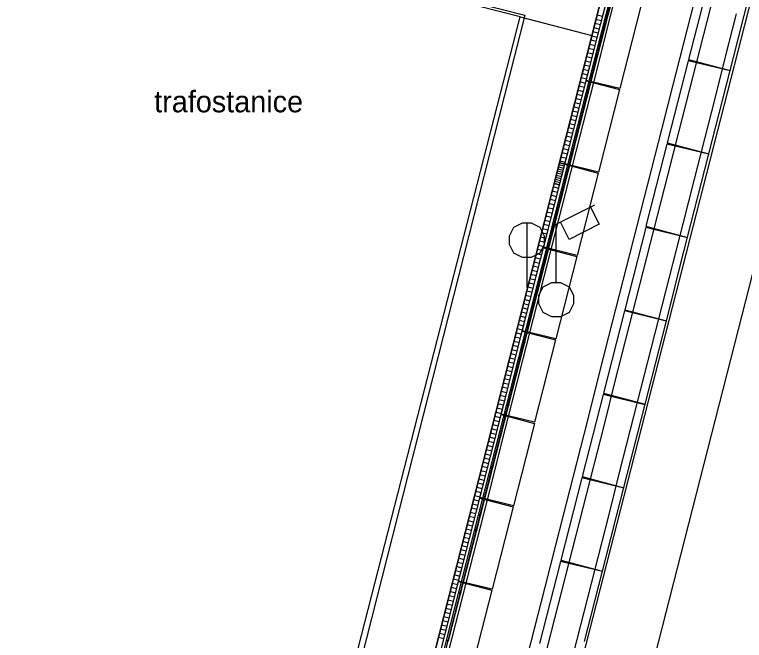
# Model space of a CAD drawing. Extents: x -733601 to -733291, y -1137892 to -1137187.
# Drawn here: x -733477.5 to -733460.56, y -1137708.26 to -1137693.72 of the extents above; entities that cross this region are included whole.
import ezdxf

# ---------------------------------------------------------------- set-up
doc = ezdxf.new("R2010")
doc.units = 0
doc.layers.add('SIT_PUV_BUS', color=7, linetype='Continuous')
doc.layers.add('SIT_PUV_ZELEZNICE', color=7, linetype='Continuous')

msp = doc.modelspace()

# ---------------------------------------------------------------- linework, layer by layer
at = {"layer": 'SIT_PUV_BUS'}
for p, q in [((-733452.43, -1137662.15), (-733466.53, -1137717.32)), ((-733460.18, -1137679.73), (-733469.47, -1137716.2)), ((-733477.5, -1137690.71), (-733465.66, -1137693.73)), ((-733465.66, -1137693.73), (-733470.86, -1137714.23)), ((-733464.93, -1137698.59), (-733464.03, -1137698.14)), ((-733464.13, -1137698.19), (-733463.93, -1137698.59)), ((-733465.91, -1137698.66), (-733465.71, -1137698.56)), ((-733465.71, -1137698.56), (-733465.51, -1137698.56)), ((-733465.61, -1137698.56), (-733465.61, -1137700.06)), ((-733465.51, -1137698.56), (-733465.31, -1137698.66)), ((-733464.93, -1137699.94), (-733464.93, -1137698.59)), ((-733464.63, -1137698.94), (-733464.83, -1137698.54)), ((-733463.93, -1137698.59), (-733464.63, -1137698.94)), ((-733466.01, -1137698.86), (-733465.91, -1137698.66)), ((-733465.31, -1137698.66), (-733465.21, -1137698.86)), ((-733466.01, -1137699.06), (-733466.01, -1137698.86)), ((-733465.21, -1137698.86), (-733465.21, -1137699.06)), ((-733465.91, -1137699.26), (-733466.01, -1137699.06)), ((-733465.21, -1137699.06), (-733465.31, -1137699.26)), ((-733465.71, -1137699.36), (-733465.91, -1137699.26)), ((-733465.31, -1137699.26), (-733465.51, -1137699.36)), ((-733465.51, -1137699.36), (-733465.71, -1137699.36)), ((-733465.23, -1137700.04), (-733465.03, -1137699.94)), ((-733465.03, -1137699.94), (-733464.83, -1137699.94)), ((-733464.83, -1137699.94), (-733464.63, -1137700.04)), ((-733465.33, -1137700.24), (-733465.23, -1137700.04)), ((-733464.63, -1137700.04), (-733464.53, -1137700.24)), ((-733465.33, -1137700.44), (-733465.33, -1137700.24)), ((-733464.53, -1137700.24), (-733464.53, -1137700.44)), ((-733465.23, -1137700.64), (-733465.33, -1137700.44)), ((-733464.53, -1137700.44), (-733464.63, -1137700.64)), ((-733465.03, -1137700.74), (-733465.23, -1137700.64)), ((-733464.63, -1137700.64), (-733464.83, -1137700.74)), ((-733464.83, -1137700.74), (-733465.03, -1137700.74))]:
    msp.add_line(p, q, dxfattribs=at)
at = {"layer": 'SIT_PUV_ZELEZNICE'}
for p, q in [((-733463.769, -1137693.72), (-733463.028, -1137690.812)), ((-733463.722, -1137693.732), (-733462.982, -1137690.824)), ((-733461.371, -1137692.852), (-733461.858, -1137694.761)), ((-733462.967, -1137693.525), (-733463.454, -1137695.437)), ((-733464.509, -1137696.627), (-733463.769, -1137693.72)), ((-733463.769, -1137693.72), (-733463.722, -1137693.732)), ((-733463.722, -1137693.732), (-733463.769, -1137693.72)), ((-733465.765, -1137693.775), (-733464.1, -1137694.204)), ((-733464.463, -1137696.639), (-733463.722, -1137693.732)), ((-733463.879, -1137693.863), (-733464.005, -1137693.831)), ((-733463.854, -1137693.766), (-733463.98, -1137693.734)), ((-733463.928, -1137694.057), (-733464.054, -1137694.025)), ((-733463.903, -1137693.96), (-733464.029, -1137693.928)), ((-733463.977, -1137694.251), (-733464.103, -1137694.219)), ((-733463.953, -1137694.154), (-733464.079, -1137694.122)), ((-733464.002, -1137694.348), (-733464.128, -1137694.316)), ((-733464.051, -1137694.541), (-733464.177, -1137694.509)), ((-733464.027, -1137694.445), (-733464.153, -1137694.412)), ((-733464.101, -1137694.735), (-733464.227, -1137694.703)), ((-733464.076, -1137694.638), (-733464.202, -1137694.606)), ((-733464.15, -1137694.929), (-733464.276, -1137694.897)), ((-733464.125, -1137694.832), (-733464.251, -1137694.8)), ((-733461.865, -1137694.79), (-733462.351, -1137696.699)), ((-733460.894, -1137695.027), (-733461.865, -1137694.79)), ((-733461.858, -1137694.761), (-733460.891, -1137695.018)), ((-733464.175, -1137695.026), (-733464.301, -1137694.994)), ((-733464.224, -1137695.22), (-733464.35, -1137695.188)), ((-733464.199, -1137695.123), (-733464.325, -1137695.091)), ((-733463.454, -1137695.437), (-733464.231, -1137695.248)), ((-733464.274, -1137695.414), (-733464.4, -1137695.382)), ((-733464.249, -1137695.317), (-733464.375, -1137695.285)), ((-733464.234, -1137695.257), (-733463.46, -1137695.463)), ((-733464.323, -1137695.607), (-733464.449, -1137695.575)), ((-733464.298, -1137695.511), (-733464.424, -1137695.478)), ((-733463.46, -1137695.463), (-733463.948, -1137697.376)), ((-733464.348, -1137695.704), (-733464.474, -1137695.672)), ((-733464.397, -1137695.898), (-733464.523, -1137695.866)), ((-733464.372, -1137695.801), (-733464.498, -1137695.769)), ((-733464.446, -1137696.092), (-733464.572, -1137696.06)), ((-733464.422, -1137695.995), (-733464.548, -1137695.963)), ((-733464.496, -1137696.286), (-733464.622, -1137696.254)), ((-733464.471, -1137696.189), (-733464.597, -1137696.157)), ((-733464.52, -1137696.383), (-733464.646, -1137696.351)), ((-733464.57, -1137696.576), (-733464.696, -1137696.544)), ((-733464.545, -1137696.48), (-733464.671, -1137696.447)), ((-733465.25, -1137699.534), (-733464.509, -1137696.627)), ((-733465.203, -1137699.546), (-733464.463, -1137696.639)), ((-733464.619, -1137696.77), (-733464.745, -1137696.738)), ((-733464.594, -1137696.673), (-733464.72, -1137696.641)), ((-733464.509, -1137696.627), (-733464.463, -1137696.639)), ((-733464.463, -1137696.639), (-733464.509, -1137696.627)), ((-733462.359, -1137696.728), (-733462.845, -1137698.637)), ((-733461.387, -1137696.965), (-733462.359, -1137696.728)), ((-733462.351, -1137696.699), (-733461.385, -1137696.956)), ((-733464.668, -1137696.964), (-733464.794, -1137696.932)), ((-733464.644, -1137696.867), (-733464.77, -1137696.835)), ((-733464.693, -1137697.061), (-733464.819, -1137697.029)), ((-733464.752, -1137697.292), (-733464.878, -1137697.26)), ((-733464.74, -1137697.244), (-733464.866, -1137697.211)), ((-733464.727, -1137697.195), (-733464.853, -1137697.163)), ((-733464.852, -1137697.159), (-733464.726, -1137697.191)), ((-733464.718, -1137697.158), (-733464.844, -1137697.126)), ((-733464.727, -1137697.196), (-733463.954, -1137697.401)), ((-733463.948, -1137697.376), (-733464.725, -1137697.186)), ((-733464.801, -1137697.486), (-733464.927, -1137697.454)), ((-733464.789, -1137697.437), (-733464.915, -1137697.405)), ((-733464.777, -1137697.389), (-733464.903, -1137697.357)), ((-733464.764, -1137697.34), (-733464.89, -1137697.308)), ((-733463.954, -1137697.401), (-733464.441, -1137699.314)), ((-733464.838, -1137697.631), (-733464.964, -1137697.599)), ((-733464.826, -1137697.583), (-733464.952, -1137697.551)), ((-733464.814, -1137697.534), (-733464.94, -1137697.502)), ((-733464.87, -1137697.756), (-733464.996, -1137697.724)), ((-733464.976, -1137697.643), (-733464.85, -1137697.675)), ((-733464.92, -1137697.95), (-733465.045, -1137697.917)), ((-733464.895, -1137697.853), (-733465.021, -1137697.821)), ((-733464.969, -1137698.143), (-733465.095, -1137698.111)), ((-733464.944, -1137698.046), (-733465.07, -1137698.014)), ((-733464.994, -1137698.24), (-733465.12, -1137698.208)), ((-733465.043, -1137698.434), (-733465.169, -1137698.402)), ((-733465.018, -1137698.337), (-733465.144, -1137698.305)), ((-733465.092, -1137698.628), (-733465.218, -1137698.596)), ((-733465.068, -1137698.531), (-733465.194, -1137698.499)), ((-733462.845, -1137698.637), (-733461.878, -1137698.894)), ((-733465.142, -1137698.822), (-733465.268, -1137698.79)), ((-733465.117, -1137698.725), (-733465.243, -1137698.693)), ((-733462.852, -1137698.666), (-733463.339, -1137700.575)), ((-733461.881, -1137698.903), (-733462.852, -1137698.666)), ((-733465.166, -1137698.919), (-733465.292, -1137698.886)), ((-733465.216, -1137699.112), (-733465.342, -1137699.08)), ((-733465.191, -1137699.015), (-733465.317, -1137698.983)), ((-733465.221, -1137699.134), (-733464.448, -1137699.339)), ((-733464.441, -1137699.314), (-733465.219, -1137699.124)), ((-733465.265, -1137699.306), (-733465.391, -1137699.274)), ((-733465.24, -1137699.209), (-733465.366, -1137699.177)), ((-733465.314, -1137699.5), (-733465.44, -1137699.468)), ((-733465.29, -1137699.403), (-733465.416, -1137699.371)), ((-733464.448, -1137699.339), (-733464.935, -1137701.252)), ((-733465.991, -1137702.441), (-733465.25, -1137699.534)), ((-733465.944, -1137702.453), (-733465.203, -1137699.546)), ((-733465.339, -1137699.597), (-733465.465, -1137699.565)), ((-733465.25, -1137699.534), (-733465.203, -1137699.546)), ((-733465.203, -1137699.546), (-733465.25, -1137699.534)), ((-733465.389, -1137699.791), (-733465.515, -1137699.759)), ((-733465.364, -1137699.694), (-733465.49, -1137699.662)), ((-733465.438, -1137699.985), (-733465.564, -1137699.952)), ((-733465.413, -1137699.888), (-733465.539, -1137699.856)), ((-733465.487, -1137700.178), (-733465.613, -1137700.146)), ((-733465.463, -1137700.081), (-733465.589, -1137700.049)), ((-733465.512, -1137700.275), (-733465.638, -1137700.243)), ((-733465.561, -1137700.469), (-733465.687, -1137700.437)), ((-733465.537, -1137700.372), (-733465.663, -1137700.34)), ((-733465.611, -1137700.663), (-733465.737, -1137700.631)), ((-733465.586, -1137700.566), (-733465.712, -1137700.534)), ((-733463.346, -1137700.604), (-733463.833, -1137702.513)), ((-733462.375, -1137700.842), (-733463.346, -1137700.604)), ((-733463.339, -1137700.575), (-733462.372, -1137700.832)), ((-733465.66, -1137700.857), (-733465.786, -1137700.825)), ((-733465.635, -1137700.76), (-733465.761, -1137700.728)), ((-733465.685, -1137700.954), (-733465.811, -1137700.921)), ((-733465.734, -1137701.147), (-733465.86, -1137701.115)), ((-733465.709, -1137701.05), (-733465.835, -1137701.018)), ((-733465.715, -1137701.072), (-733464.942, -1137701.277)), ((-733464.935, -1137701.252), (-733465.712, -1137701.062)), ((-733465.784, -1137701.341), (-733465.909, -1137701.309)), ((-733465.759, -1137701.244), (-733465.885, -1137701.212)), ((-733464.942, -1137701.277), (-733465.429, -1137703.19)), ((-733465.833, -1137701.535), (-733465.959, -1137701.503)), ((-733465.808, -1137701.438), (-733465.934, -1137701.406)), ((-733465.858, -1137701.632), (-733465.984, -1137701.6)), ((-733465.907, -1137701.826), (-733466.033, -1137701.794)), ((-733465.882, -1137701.729), (-733466.008, -1137701.697)), ((-733465.956, -1137702.02), (-733466.082, -1137701.987)), ((-733465.932, -1137701.923), (-733466.058, -1137701.891)), ((-733466.006, -1137702.213), (-733466.132, -1137702.181)), ((-733465.981, -1137702.116), (-733466.107, -1137702.084)), ((-733466.03, -1137702.31), (-733466.156, -1137702.278)), ((-733466.731, -1137705.348), (-733465.991, -1137702.441)), ((-733466.684, -1137705.36), (-733465.944, -1137702.453)), ((-733466.08, -1137702.504), (-733466.206, -1137702.472)), ((-733466.055, -1137702.407), (-733466.181, -1137702.375)), ((-733465.991, -1137702.441), (-733465.944, -1137702.453)), ((-733465.944, -1137702.453), (-733465.991, -1137702.441)), ((-733463.833, -1137702.513), (-733462.866, -1137702.77)), ((-733466.129, -1137702.698), (-733466.255, -1137702.666)), ((-733466.104, -1137702.601), (-733466.23, -1137702.569)), ((-733463.84, -1137702.542), (-733464.326, -1137704.452)), ((-733462.868, -1137702.78), (-733463.84, -1137702.542)), ((-733466.178, -1137702.892), (-733466.304, -1137702.86)), ((-733466.154, -1137702.795), (-733466.28, -1137702.763)), ((-733466.203, -1137702.989), (-733466.329, -1137702.957)), ((-733466.209, -1137703.01), (-733465.435, -1137703.215)), ((-733465.429, -1137703.19), (-733466.206, -1137703)), ((-733466.253, -1137703.182), (-733466.379, -1137703.15)), ((-733466.228, -1137703.085), (-733466.354, -1137703.053)), ((-733465.435, -1137703.215), (-733465.923, -1137705.128)), ((-733466.302, -1137703.376), (-733466.428, -1137703.344)), ((-733466.277, -1137703.279), (-733466.403, -1137703.247)), ((-733466.351, -1137703.57), (-733466.477, -1137703.538)), ((-733466.327, -1137703.473), (-733466.453, -1137703.441)), ((-733466.376, -1137703.667), (-733466.502, -1137703.635)), ((-733466.425, -1137703.861), (-733466.551, -1137703.829)), ((-733466.401, -1137703.764), (-733466.527, -1137703.732)), ((-733466.475, -1137704.055), (-733466.601, -1137704.022)), ((-733466.45, -1137703.958), (-733466.576, -1137703.926)), ((-733466.524, -1137704.248), (-733466.65, -1137704.216)), ((-733466.499, -1137704.151), (-733466.625, -1137704.119)), ((-733466.549, -1137704.345), (-733466.675, -1137704.313)), ((-733466.598, -1137704.539), (-733466.724, -1137704.507)), ((-733466.573, -1137704.442), (-733466.699, -1137704.41)), ((-733464.334, -1137704.481), (-733464.82, -1137706.39)), ((-733463.362, -1137704.718), (-733464.334, -1137704.481)), ((-733464.326, -1137704.452), (-733463.36, -1137704.708)), ((-733466.648, -1137704.733), (-733466.773, -1137704.701)), ((-733466.623, -1137704.636), (-733466.749, -1137704.604)), ((-733466.697, -1137704.927), (-733466.823, -1137704.895)), ((-733466.672, -1137704.83), (-733466.798, -1137704.798)), ((-733466.722, -1137705.024), (-733466.848, -1137704.992)), ((-733466.702, -1137704.948), (-733465.929, -1137705.153)), ((-733465.923, -1137705.128), (-733466.7, -1137704.938)), ((-733466.771, -1137705.217), (-733466.897, -1137705.185)), ((-733466.746, -1137705.121), (-733466.872, -1137705.088)), ((-733465.929, -1137705.153), (-733466.416, -1137707.066)), ((-733467.472, -1137708.255), (-733466.731, -1137705.348)), ((-733467.425, -1137708.267), (-733466.684, -1137705.36)), ((-733466.82, -1137705.411), (-733466.946, -1137705.379)), ((-733466.796, -1137705.314), (-733466.922, -1137705.282)), ((-733466.731, -1137705.348), (-733466.684, -1137705.36)), ((-733466.684, -1137705.36), (-733466.731, -1137705.348)), ((-733466.87, -1137705.605), (-733466.996, -1137705.573)), ((-733466.845, -1137705.508), (-733466.971, -1137705.476)), ((-733466.894, -1137705.702), (-733467.02, -1137705.67)), ((-733466.944, -1137705.896), (-733467.07, -1137705.864)), ((-733466.919, -1137705.799), (-733467.045, -1137705.767)), ((-733466.993, -1137706.09), (-733467.119, -1137706.057)), ((-733466.968, -1137705.993), (-733467.094, -1137705.961)), ((-733467.042, -1137706.283), (-733467.168, -1137706.251)), ((-733467.018, -1137706.186), (-733467.144, -1137706.154)), ((-733467.067, -1137706.38), (-733467.193, -1137706.348)), ((-733464.827, -1137706.419), (-733465.314, -1137708.328)), ((-733463.856, -1137706.656), (-733464.827, -1137706.419)), ((-733464.82, -1137706.39), (-733463.853, -1137706.646)), ((-733467.117, -1137706.574), (-733467.243, -1137706.542)), ((-733467.092, -1137706.477), (-733467.218, -1137706.445)), ((-733467.166, -1137706.768), (-733467.292, -1137706.736)), ((-733467.141, -1137706.671), (-733467.267, -1137706.639)), ((-733467.215, -1137706.962), (-733467.341, -1137706.93)), ((-733467.191, -1137706.865), (-733467.317, -1137706.833)), ((-733467.196, -1137706.886), (-733466.423, -1137707.091)), ((-733466.416, -1137707.066), (-733467.194, -1137706.876)), ((-733467.24, -1137707.059), (-733467.366, -1137707.027)), ((-733466.423, -1137707.091), (-733466.91, -1137709.004)), ((-733467.289, -1137707.252), (-733467.415, -1137707.22)), ((-733467.265, -1137707.156), (-733467.391, -1137707.123)), ((-733467.339, -1137707.446), (-733467.465, -1137707.414)), ((-733467.314, -1137707.349), (-733467.44, -1137707.317)), ((-733467.388, -1137707.64), (-733467.514, -1137707.608)), ((-733467.363, -1137707.543), (-733467.489, -1137707.511)), ((-733467.413, -1137707.737), (-733467.539, -1137707.705)), ((-733467.462, -1137707.931), (-733467.588, -1137707.899)), ((-733467.437, -1137707.834), (-733467.563, -1137707.802)), ((-733467.512, -1137708.125), (-733467.637, -1137708.092)), ((-733467.487, -1137708.028), (-733467.613, -1137707.996)), ((-733468.212, -1137711.163), (-733467.472, -1137708.255)), ((-733467.536, -1137708.221), (-733467.662, -1137708.189)), ((-733467.472, -1137708.255), (-733467.425, -1137708.267)), ((-733467.425, -1137708.267), (-733467.472, -1137708.255))]:
    msp.add_line(p, q, dxfattribs=at)
for points in [[(-733473.591, -1137751.638), (-733472.603, -1137747.76), (-733470.135, -1137738.069), (-733467.666, -1137728.379), (-733465.198, -1137718.688), (-733462.729, -1137708.998), (-733460.26, -1137699.307), (-733457.792, -1137689.617), (-733455.323, -1137679.926), (-733452.855, -1137670.236), (-733450.386, -1137660.545), (-733448.734, -1137654.061), (-733447.917, -1137650.855), (-733445.432, -1137641.168), (-733442.928, -1137631.487), (-733440.405, -1137621.811), (-733437.862, -1137612.139), (-733437.8, -1137611.906), (-733435.314, -1137602.469), (-733432.775, -1137592.797), (-733432.613, -1137592.177)], [(-733469.666, -1137716.055), (-733462.877, -1137689.406)], [(-733470.978, -1137714.118), (-733465.765, -1137693.775), (-733471.431, -1137692.323)], [(-733464.27, -1137708.28), (-733464.023, -1137707.311), (-733463.776, -1137706.342), (-733463.529, -1137705.373), (-733463.282, -1137704.404), (-733463.035, -1137703.435), (-733462.788, -1137702.466), (-733462.542, -1137701.496), (-733462.295, -1137700.527), (-733462.048, -1137699.558), (-733461.801, -1137698.589), (-733461.554, -1137697.62), (-733461.307, -1137696.651), (-733461.06, -1137695.682), (-733460.814, -1137694.713), (-733460.567, -1137693.744), (-733460.32, -1137692.775)], [(-733467.598, -1137708.464), (-733467.351, -1137707.495), (-733467.104, -1137706.526), (-733466.857, -1137705.557), (-733466.611, -1137704.588), (-733466.364, -1137703.619), (-733466.117, -1137702.65), (-733465.87, -1137701.681), (-733465.623, -1137700.711), (-733465.376, -1137699.742), (-733465.129, -1137698.773), (-733464.883, -1137697.804), (-733464.636, -1137696.835), (-733464.389, -1137695.866), (-733464.142, -1137694.897), (-733463.895, -1137693.928), (-733463.648, -1137692.959)], [(-733467.43, -1137708.532), (-733467.183, -1137707.563), (-733466.936, -1137706.594), (-733466.689, -1137705.625), (-733466.442, -1137704.656), (-733466.195, -1137703.687), (-733465.948, -1137702.718), (-733465.702, -1137701.749), (-733465.455, -1137700.78), (-733465.208, -1137699.81), (-733464.961, -1137698.841), (-733464.714, -1137697.872), (-733464.467, -1137696.903), (-733464.22, -1137695.934), (-733463.974, -1137694.965), (-733463.727, -1137693.996), (-733463.48, -1137693.027)], [(-733465.679, -1137708.953), (-733465.432, -1137707.984), (-733465.186, -1137707.015), (-733464.939, -1137706.046), (-733464.692, -1137705.076), (-733464.445, -1137704.107), (-733464.198, -1137703.138), (-733463.951, -1137702.169), (-733463.704, -1137701.2), (-733463.458, -1137700.231), (-733463.211, -1137699.262), (-733462.964, -1137698.293), (-733462.717, -1137697.324), (-733462.47, -1137696.355), (-733462.223, -1137695.386), (-733461.976, -1137694.417), (-733461.73, -1137693.448)], [(-733465.292, -1137709.051), (-733465.045, -1137708.082), (-733464.798, -1137707.113), (-733464.551, -1137706.144), (-733464.304, -1137705.175), (-733464.057, -1137704.206), (-733463.81, -1137703.237), (-733463.564, -1137702.268), (-733463.317, -1137701.299), (-733463.07, -1137700.33), (-733462.823, -1137699.361), (-733462.576, -1137698.392), (-733462.329, -1137697.423), (-733462.082, -1137696.454), (-733461.836, -1137695.485), (-733461.589, -1137694.516), (-733461.342, -1137693.547)], [(-733464.691, -1137709.204), (-733464.444, -1137708.235), (-733464.197, -1137707.266), (-733463.95, -1137706.297), (-733463.703, -1137705.328), (-733463.457, -1137704.359), (-733463.21, -1137703.39), (-733462.963, -1137702.421), (-733462.716, -1137701.452), (-733462.469, -1137700.483), (-733462.222, -1137699.514), (-733461.975, -1137698.545), (-733461.729, -1137697.576), (-733461.482, -1137696.607), (-733461.235, -1137695.638), (-733460.988, -1137694.669), (-733460.741, -1137693.7)], [(-733467.598, -1137708.464), (-733467.351, -1137707.495), (-733467.196, -1137706.886), (-733467.194, -1137706.876), (-733467.104, -1137706.526), (-733466.857, -1137705.557), (-733466.702, -1137704.948), (-733466.7, -1137704.938), (-733466.611, -1137704.588), (-733466.364, -1137703.619), (-733466.209, -1137703.01), (-733466.206, -1137703), (-733466.117, -1137702.65), (-733465.87, -1137701.681), (-733465.715, -1137701.072), (-733465.712, -1137701.062), (-733465.623, -1137700.711), (-733465.376, -1137699.742), (-733465.221, -1137699.134), (-733465.219, -1137699.124), (-733465.129, -1137698.773), (-733464.883, -1137697.804), (-733464.85, -1137697.675), (-733464.976, -1137697.643), (-733469.666, -1137716.055)]]:
    msp.add_lwpolyline(points, dxfattribs=at)
for points in [[(-733462.751, -1137689.438), (-733462.877, -1137689.406), (-733464.852, -1137697.159), (-733464.726, -1137697.191), (-733464.725, -1137697.186), (-733464.636, -1137696.835), (-733464.389, -1137695.866), (-733464.234, -1137695.257), (-733464.231, -1137695.248), (-733464.142, -1137694.897), (-733463.895, -1137693.928), (-733463.74, -1137693.319), (-733463.738, -1137693.31), (-733463.648, -1137692.959), (-733463.401, -1137691.99), (-733463.246, -1137691.381), (-733463.244, -1137691.372), (-733463.155, -1137691.021), (-733462.908, -1137690.052), (-733462.753, -1137689.443)], [(-733464.726, -1137697.191), (-733464.852, -1137697.159), (-733464.976, -1137697.643), (-733464.85, -1137697.675), (-733464.727, -1137697.196)]]:
    msp.add_lwpolyline(points, close=True, dxfattribs=at)
for centre in [(-733463.832, -1137694.065), (-733464.202, -1137695.518), (-733464.572, -1137696.972), (-733464.943, -1137698.425), (-733465.313, -1137699.879), (-733465.683, -1137701.333), (-733466.054, -1137702.786), (-733466.424, -1137704.24), (-733466.794, -1137705.693), (-733467.164, -1137707.147)]:
    msp.add_circle(centre, 0.0241, dxfattribs=at)

# ---------------------------------------------------------------- texts
at = {"layer": 'SIT_PUV_BUS'}
msp.add_text('trafostanice', height=0.5, dxfattribs=at).set_placement((-733474.26, -1137695.99))

doc.saveas('drawing.dxf')
